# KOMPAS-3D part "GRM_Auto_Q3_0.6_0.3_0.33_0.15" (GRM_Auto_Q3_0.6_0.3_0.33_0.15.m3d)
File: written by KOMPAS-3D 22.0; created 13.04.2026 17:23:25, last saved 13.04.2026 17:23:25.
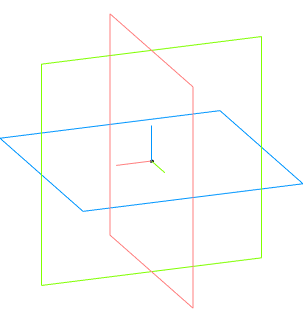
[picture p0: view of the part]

Document properties: Автор: Andrey; Полное имя файла: C:\Users\User1\Documents\GRM_Auto_Q3_0.6_0.3_0.33_0.15.m3d

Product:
- Part/product: GRM_Auto_Q3_0.6_0.3_0.33_0.15

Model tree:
1. Операция без истории:1
2. Операция без истории:2
3. Операция без истории:3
